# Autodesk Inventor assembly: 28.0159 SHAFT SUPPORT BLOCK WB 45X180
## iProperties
Created: 2007-06
Part Number: 28.0159 SHAFT SUPPORT BLOCK WB 45X180
Document SubType Name: Assembly
Designer: Andy Moles
Author: Andy Moles
